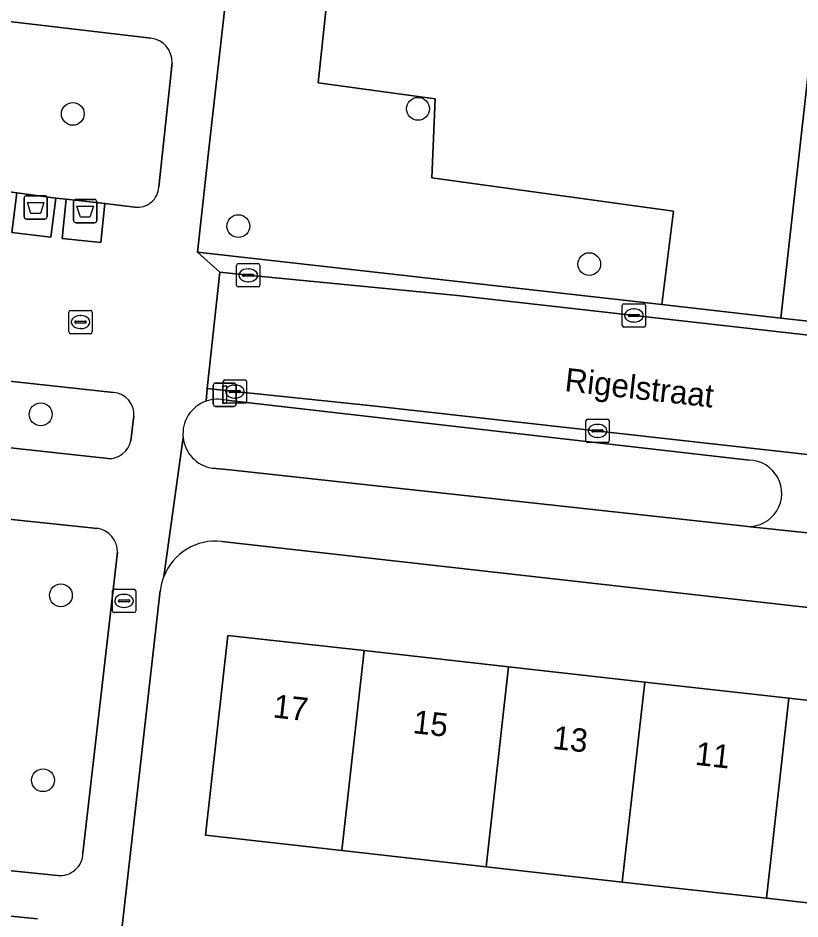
# Model space of a CAD drawing. Extents: x 161928 to 163071, y 386474 to 387428.
# Drawn here: x 162089.79 to 162123.29, y 386856.66 to 386895.27 of the extents above; entities that cross this region are included whole.
import ezdxf

# ---------------------------------------------------------------- set-up
doc = ezdxf.new("R2010")
doc.units = 0
for name, color, linetype in [('IMGEO_Afval_apart_plaats', 7, 'Continuous'), ('IMGEO_Boom', 7, 'Continuous'), ('IMGEO_Brandkraan', 7, 'Continuous'), ('IMGEO_Erf', 7, 'Continuous'), ('IMGEO_Groenvoorziening', 7, 'Continuous'), ('IMGEO_Kolk', 7, 'Continuous'), ('IMGEO_Lichtmast', 7, 'Continuous'), ('IMGEO_Openbare_ruimte_label', 7, 'Continuous'), ('IMGEO_Pand', 7, 'Continuous'), ('IMGEO_Pand_nummerreeks', 7, 'Continuous'), ('IMGEO_Parkeervlak_open', 7, 'Continuous'), ('IMGEO_Rijbaan_lokaal_open', 7, 'Continuous'), ('IMGEO_Voetpad_gesloten', 7, 'Continuous'), ('IMGEO_Voetpad_open', 7, 'Continuous')]:
    doc.layers.add(name, color=color, linetype=linetype)

msp = doc.modelspace()

# ---------------------------------------------------------------- linework, layer by layer
at = {"layer": 'IMGEO_Afval_apart_plaats'}
for p, q in [((162090.152, 386887.655), (162090.942, 386887.655)), ((162090.942, 386887.655), (162090.152, 386887.655)), ((162090.052, 386886.755), (162090.052, 386887.555)), ((162090.052, 386887.555), (162090.052, 386886.755)), ((162091.042, 386887.555), (162091.042, 386886.755)), ((162091.042, 386886.755), (162091.042, 386887.555)), ((162092.177, 386886.595), (162092.177, 386887.395)), ((162092.177, 386887.395), (162092.177, 386886.595)), ((162092.277, 386887.495), (162093.067, 386887.495)), ((162093.067, 386887.495), (162092.277, 386887.495)), ((162093.167, 386887.395), (162093.167, 386886.595)), ((162093.167, 386886.595), (162093.167, 386887.395)), ((162090.942, 386886.655), (162090.152, 386886.655)), ((162090.152, 386886.655), (162090.942, 386886.655)), ((162093.067, 386886.495), (162092.277, 386886.495)), ((162092.277, 386886.495), (162093.067, 386886.495))]:
    msp.add_line(p, q, dxfattribs=at)
for points in [[(162090.195, 386887.369), (162090.899, 386887.369), (162090.75, 386886.899), (162090.344, 386886.899), (162090.195, 386887.369)], [(162092.32, 386887.209), (162093.024, 386887.209), (162092.875, 386886.739), (162092.469, 386886.739), (162092.32, 386887.209)]]:
    msp.add_lwpolyline(points, dxfattribs=at)
for centre, start, end in [((162090.152, 386887.555), 90, 180), ((162090.152, 386887.555), 90, 180), ((162090.942, 386887.555), 0, 90), ((162090.942, 386887.555), 360, 90), ((162092.277, 386887.395), 90, 180), ((162092.277, 386887.395), 90, 180), ((162093.067, 386887.395), 0, 90), ((162093.067, 386887.395), 360, 90), ((162090.152, 386886.755), 180, 270), ((162090.152, 386886.755), 180, 270), ((162090.942, 386886.755), 270, 0), ((162090.942, 386886.755), 270, 0), ((162092.277, 386886.595), 180, 270), ((162092.277, 386886.595), 180, 270), ((162093.067, 386886.595), 270, 0), ((162093.067, 386886.595), 270, 0)]:
    msp.add_arc(centre, 0.1, start, end, dxfattribs=at)
at = {"layer": 'IMGEO_Boom'}
for centre in [(162106.929, 386891.379), (162092.141, 386891.163), (162099.233, 386886.351), (162114.266, 386884.723), (162090.766, 386878.286), (162091.629, 386870.53), (162090.864, 386862.606)]:
    msp.add_circle(centre, 0.489, dxfattribs=at)
at = {"layer": 'IMGEO_Brandkraan'}
for p, q in [((162093.835, 386869.864), (162093.835, 386870.716)), ((162093.91, 386870.79), (162094.762, 386870.79)), ((162094.323, 386870.57), (162094.348, 386870.57)), ((162094.836, 386870.716), (162094.836, 386869.864)), ((162094.094, 386870.284), (162094.094, 386870.296)), ((162094.532, 386870.247), (162094.134, 386870.247)), ((162094.137, 386870.333), (162094.535, 386870.333)), ((162094.578, 386870.296), (162094.578, 386870.284)), ((162094.346, 386870.01), (162094.321, 386870.01)), ((162094.762, 386869.79), (162093.91, 386869.79))]:
    msp.add_line(p, q, dxfattribs=at)
for points in [[(162093.835, 386869.864), (162093.835, 386870.716)], [(162093.91, 386870.79), (162094.762, 386870.79)], [(162094.836, 386870.716), (162094.836, 386869.864)], [(162094.762, 386869.79), (162093.91, 386869.79)]]:
    msp.add_lwpolyline(points, dxfattribs=at)
for centre, radius, start, end in [((162093.912, 386870.714), 0.0765, 91.552, 178.448), ((162093.912, 386870.714), 0.0765, 91.552, 178.448), ((162094.76, 386870.714), 0.0765, 1.552, 88.448), ((162094.76, 386870.714), 0.0765, 1.552, 88.448), ((162094.134, 386870.293), 0.0403, 85.8775, 175.7526), ((162094.131, 386870.283), 0.0366, 178.938, 274.7102), ((162094.535, 386870.29), 0.043, 264.8664, 352.4533), ((162094.539, 386870.295), 0.0386, 1.7309, 96.639), ((162093.912, 386869.866), 0.0765, 181.552, 268.448), ((162093.912, 386869.866), 0.0765, 181.552, 268.448), ((162094.76, 386869.866), 0.0765, 271.552, 358.448), ((162094.76, 386869.866), 0.0765, 271.552, 358.448)]:
    msp.add_arc(centre, radius, start, end, dxfattribs=at)
for centre, major_axis, ratio, start_param, end_param in [((162094.322, 386870.29), (-0.387, 0.002), 0.722429, 4.712389, 7.853982), ((162094.347, 386870.29), (-0.39, 0.002), 0.717154, 1.570796, 4.712389)]:
    msp.add_ellipse(centre, major_axis=major_axis, ratio=ratio, start_param=start_param, end_param=end_param, dxfattribs=at)
at = {"layer": 'IMGEO_Erf'}
for points in [[(162154.85, 386866.488), (162098.526, 386872.838)], [(162095.89, 386870.733), (162093.586, 386850.424), (162103.999, 386849.243), (162104.273, 386851.973), (162109.039, 386851.496), (162114.238, 386850.974), (162113.968, 386848.281), (162115.579, 386848.12), (162115.42, 386846.626), (162113.747, 386846.805), (162113.411, 386843.657), (162108.186, 386844.214), (162103.812, 386844.68), (162104.152, 386847.876), (162101.178, 386848.193), (162100.878, 386845.559), (162096.111, 386846.102), (162095.376, 386838.682), (162101.521, 386837.997), (162107.523, 386837.329), (162113.432, 386836.67), (162119.351, 386836.011), (162125.329, 386835.345)], [(162151.734, 386854.186), (162145.677, 386854.867), (162139.524, 386855.559), (162133.579, 386856.227), (162127.731, 386856.885), (162121.856, 386857.546), (162115.68, 386858.24), (162109.845, 386858.896), (162103.662, 386859.592), (162097.824, 386860.248), (162098.786, 386868.814), (162104.624, 386868.159), (162110.807, 386867.465), (162116.642, 386866.809), (162122.818, 386866.116), (162128.694, 386865.457), (162134.542, 386864.8), (162140.487, 386864.133), (162146.64, 386863.442), (162152.697, 386862.762), (162156.622, 386862.323), (162156.814, 386864.022)]]:
    msp.add_lwpolyline(points, dxfattribs=at)
for centre, radius, start, end in [((162098.259, 386870.469), 2.384, 83.5771, 158.6009), ((162098.249, 386870.471), 2.373, 158.5401, 173.6545)]:
    msp.add_arc(centre, radius, start, end, dxfattribs=at)
at = {"layer": 'IMGEO_Groenvoorziening'}
for points in [[(162124.115, 386897.125), (162124.371, 386899.169), (162124.713, 386901.768), (162124.945, 386903.531), (162126.97, 386903.362), (162127.276, 386905.919), (162127.685, 386909.558), (162125.661, 386909.778), (162104.628, 386912.06), (162106.651, 386930.715), (162107.583, 386930.614), (162108.784, 386940.868), (162103.8, 386941.487), (162099.956, 386907.286), (162104.146, 386906.641), (162102.651, 386892.496), (162107.668, 386891.801), (162107.524, 386888.417), (162117.878, 386886.991), (162117.382, 386882.988), (162122.47, 386882.414)], [(162099.801, 386905.909), (162098.584, 386895.081), (162098.003, 386889.912), (162097.477, 386885.236), (162117.382, 386882.988), (162117.878, 386886.991), (162107.524, 386888.417), (162107.668, 386891.801), (162102.651, 386892.496), (162104.146, 386906.641), (162099.956, 386907.286)], [(162125.347, 386896.927), (162126.226, 386896.855), (162126.494, 386898.944), (162124.371, 386899.169), (162124.115, 386897.125), (162122.47, 386882.414), (162123.771, 386882.267)]]:
    msp.add_lwpolyline(points, close=True, dxfattribs=at)
for points in [[(162088.564, 386895.224), (162087.786, 386888.057), (162089.742, 386887.772), (162091.415, 386887.555), (162091.85, 386887.504), (162093.517, 386887.319), (162094.8, 386887.169)], [(162095.479, 386894.402), (162088.564, 386895.224)], [(162095.826, 386888.035), (162096.393, 386893.355)], [(162086.915, 386879.984), (162086.715, 386878.398), (162086.574, 386877.16), (162093.649, 386876.392)], [(162093.883, 386879.229), (162086.915, 386879.984)], [(162121.116, 386876.319), (162098.714, 386878.889)], [(162094.624, 386877.151), (162094.756, 386878.22)], [(162098.107, 386875.983), (162098.861, 386875.901), (162120.945, 386873.488), (162121.04, 386873.481)], [(162093.197, 386873.401), (162086.247, 386874.125), (162084.603, 386859.23), (162091.479, 386858.53)], [(162092.575, 386859.483), (162094.05, 386872.38)]]:
    msp.add_lwpolyline(points, dxfattribs=at)
for centre, radius, start, end in [((162095.369, 386893.383), 1.025, 358.414, 83.826), ((162094.916, 386888.073), 0.911, 262.6987, 357.6336), ((162093.804, 386878.278), 0.954, 356.5068, 85.2268), ((162098.343, 386877.451), 1.484, 109.351, 186.0645), ((162098.345, 386877.447), 1.488, 75.6517, 109.3908), ((162093.684, 386877.352), 0.961, 267.8829, 347.9158), ((162098.345, 386877.45), 1.486, 186.0234, 260.7881), ((162121.095, 386874.9), 1.42, 267.7809, 89.1512), ((162093.043, 386872.405), 1.008, 358.5718, 81.1828), ((162091.598, 386859.5), 0.977, 263.0077, 359.0079)]:
    msp.add_arc(centre, radius, start, end, dxfattribs=at)
at = {"layer": 'IMGEO_Kolk'}
for p, q in [((162099.158, 386883.818), (162099.158, 386884.67)), ((162099.233, 386884.744), (162100.085, 386884.744)), ((162099.646, 386884.524), (162099.671, 386884.524)), ((162100.159, 386884.67), (162100.159, 386883.818)), ((162099.417, 386884.238), (162099.417, 386884.25)), ((162099.855, 386884.201), (162099.457, 386884.201)), ((162099.46, 386884.287), (162099.858, 386884.287)), ((162099.901, 386884.25), (162099.901, 386884.238)), ((162100.085, 386883.744), (162099.233, 386883.744)), ((162099.669, 386883.964), (162099.644, 386883.964)), ((162115.68, 386882.097), (162115.68, 386882.949)), ((162115.755, 386883.023), (162116.607, 386883.023)), ((162116.681, 386882.949), (162116.681, 386882.097)), ((162091.97, 386881.816), (162091.97, 386882.668)), ((162092.045, 386882.742), (162092.897, 386882.742)), ((162092.971, 386882.668), (162092.971, 386881.816)), ((162115.982, 386882.566), (162116.38, 386882.566)), ((162116.168, 386882.803), (162116.193, 386882.803)), ((162092.229, 386882.236), (162092.229, 386882.248)), ((162092.667, 386882.199), (162092.269, 386882.199)), ((162092.272, 386882.285), (162092.67, 386882.285)), ((162092.458, 386882.522), (162092.483, 386882.522)), ((162092.713, 386882.248), (162092.713, 386882.236)), ((162115.939, 386882.517), (162115.939, 386882.529)), ((162116.377, 386882.48), (162115.979, 386882.48)), ((162116.191, 386882.243), (162116.166, 386882.243)), ((162116.423, 386882.529), (162116.423, 386882.517)), ((162092.481, 386881.962), (162092.456, 386881.962)), ((162116.607, 386882.023), (162115.755, 386882.023)), ((162092.897, 386881.742), (162092.045, 386881.742)), ((162098.583, 386878.835), (162098.583, 386879.687)), ((162098.658, 386879.761), (162099.51, 386879.761)), ((162099.071, 386879.541), (162099.096, 386879.541)), ((162099.584, 386879.687), (162099.584, 386878.835)), ((162098.842, 386879.255), (162098.842, 386879.267)), ((162099.28, 386879.218), (162098.882, 386879.218)), ((162098.885, 386879.304), (162099.283, 386879.304)), ((162099.326, 386879.267), (162099.326, 386879.255)), ((162099.51, 386878.761), (162098.658, 386878.761)), ((162099.094, 386878.981), (162099.069, 386878.981)), ((162114.122, 386877.149), (162114.122, 386878.001)), ((162114.197, 386878.075), (162115.049, 386878.075)), ((162115.123, 386878.001), (162115.123, 386877.149)), ((162114.381, 386877.569), (162114.381, 386877.581)), ((162114.819, 386877.532), (162114.421, 386877.532)), ((162114.424, 386877.618), (162114.822, 386877.618)), ((162114.61, 386877.855), (162114.635, 386877.855)), ((162114.865, 386877.581), (162114.865, 386877.569)), ((162114.633, 386877.295), (162114.608, 386877.295)), ((162115.049, 386877.075), (162114.197, 386877.075))]:
    msp.add_line(p, q, dxfattribs=at)
for points in [[(162099.158, 386883.818), (162099.158, 386884.67)], [(162099.233, 386884.744), (162100.085, 386884.744)], [(162100.159, 386884.67), (162100.159, 386883.818)], [(162100.085, 386883.744), (162099.233, 386883.744)], [(162115.68, 386882.097), (162115.68, 386882.949)], [(162115.755, 386883.023), (162116.607, 386883.023)], [(162116.681, 386882.949), (162116.681, 386882.097)], [(162091.97, 386881.816), (162091.97, 386882.668)], [(162092.045, 386882.742), (162092.897, 386882.742)], [(162092.971, 386882.668), (162092.971, 386881.816)], [(162116.607, 386882.023), (162115.755, 386882.023)], [(162092.897, 386881.742), (162092.045, 386881.742)], [(162098.583, 386878.835), (162098.583, 386879.687)], [(162098.658, 386879.761), (162099.51, 386879.761)], [(162099.584, 386879.687), (162099.584, 386878.835)], [(162099.51, 386878.761), (162098.658, 386878.761)], [(162114.122, 386877.149), (162114.122, 386878.001)], [(162114.197, 386878.075), (162115.049, 386878.075)], [(162115.123, 386878.001), (162115.123, 386877.149)], [(162115.049, 386877.075), (162114.197, 386877.075)]]:
    msp.add_lwpolyline(points, dxfattribs=at)
for centre, radius, start, end in [((162099.235, 386884.668), 0.0765, 91.552, 178.448), ((162099.235, 386884.668), 0.0765, 91.552, 178.448), ((162100.083, 386884.668), 0.0765, 1.552, 88.448), ((162100.083, 386884.668), 0.0765, 1.552, 88.448), ((162099.457, 386884.247), 0.0403, 85.8775, 175.7526), ((162099.454, 386884.237), 0.0366, 178.938, 274.7102), ((162099.858, 386884.244), 0.043, 264.8664, 352.4533), ((162099.862, 386884.249), 0.0386, 1.7309, 96.639), ((162099.235, 386883.82), 0.0765, 181.552, 268.448), ((162099.235, 386883.82), 0.0765, 181.552, 268.448), ((162100.083, 386883.82), 0.0765, 271.552, 358.448), ((162100.083, 386883.82), 0.0765, 271.552, 358.448), ((162115.757, 386882.947), 0.0765, 91.552, 178.448), ((162115.757, 386882.947), 0.0765, 91.552, 178.448), ((162116.605, 386882.947), 0.0765, 1.552, 88.448), ((162116.605, 386882.947), 0.0765, 1.552, 88.448), ((162092.047, 386882.666), 0.0765, 91.552, 178.448), ((162092.047, 386882.666), 0.0765, 91.552, 178.448), ((162092.895, 386882.666), 0.0765, 1.552, 88.448), ((162092.895, 386882.666), 0.0765, 1.552, 88.448), ((162115.979, 386882.526), 0.0403, 85.8775, 175.7526), ((162116.384, 386882.528), 0.0386, 1.7309, 96.639), ((162092.269, 386882.245), 0.0403, 85.8775, 175.7526), ((162092.266, 386882.235), 0.0366, 178.938, 274.7102), ((162092.67, 386882.242), 0.043, 264.8664, 352.4533), ((162092.674, 386882.247), 0.0386, 1.7309, 96.639), ((162115.976, 386882.516), 0.0366, 178.938, 274.7102), ((162116.38, 386882.523), 0.043, 264.8664, 352.4533), ((162092.047, 386881.818), 0.0765, 181.552, 268.448), ((162092.047, 386881.818), 0.0765, 181.552, 268.448), ((162092.895, 386881.818), 0.0765, 271.552, 358.448), ((162092.895, 386881.818), 0.0765, 271.552, 358.448), ((162115.757, 386882.099), 0.0765, 181.552, 268.448), ((162115.757, 386882.099), 0.0765, 181.552, 268.448), ((162116.605, 386882.099), 0.0765, 271.552, 358.448), ((162116.605, 386882.099), 0.0765, 271.552, 358.448), ((162098.66, 386879.685), 0.0765, 91.552, 178.448), ((162098.66, 386879.685), 0.0765, 91.552, 178.448), ((162099.508, 386879.685), 0.0765, 1.552, 88.448), ((162099.508, 386879.685), 0.0765, 1.552, 88.448), ((162098.882, 386879.264), 0.0403, 85.8775, 175.7526), ((162098.879, 386879.254), 0.0366, 178.938, 274.7102), ((162099.283, 386879.261), 0.043, 264.8664, 352.4533), ((162099.287, 386879.266), 0.0386, 1.7309, 96.639), ((162098.66, 386878.837), 0.0765, 181.552, 268.448), ((162098.66, 386878.837), 0.0765, 181.552, 268.448), ((162099.508, 386878.837), 0.0765, 271.552, 358.448), ((162099.508, 386878.837), 0.0765, 271.552, 358.448), ((162114.199, 386877.999), 0.0765, 91.552, 178.448), ((162114.199, 386877.999), 0.0765, 91.552, 178.448), ((162115.047, 386877.999), 0.0765, 1.552, 88.448), ((162115.047, 386877.999), 0.0765, 1.552, 88.448), ((162114.421, 386877.578), 0.0403, 85.8775, 175.7526), ((162114.418, 386877.568), 0.0366, 178.938, 274.7102), ((162114.822, 386877.575), 0.043, 264.8664, 352.4533), ((162114.826, 386877.58), 0.0386, 1.7309, 96.639), ((162114.199, 386877.151), 0.0765, 181.552, 268.448), ((162114.199, 386877.151), 0.0765, 181.552, 268.448), ((162115.047, 386877.151), 0.0765, 271.552, 358.448), ((162115.047, 386877.151), 0.0765, 271.552, 358.448)]:
    msp.add_arc(centre, radius, start, end, dxfattribs=at)
for centre, major_axis, ratio, start_param, end_param in [((162099.645, 386884.244), (-0.387, 0.002), 0.722429, 4.712389, 7.853982), ((162099.67, 386884.244), (-0.39, 0.002), 0.717154, 1.570796, 4.712389), ((162116.167, 386882.523), (-0.387, 0.002), 0.722429, 4.712389, 7.853982), ((162116.192, 386882.523), (-0.39, 0.002), 0.717154, 1.570796, 4.712389), ((162092.457, 386882.242), (-0.387, 0.002), 0.722429, 4.712389, 7.853982), ((162092.482, 386882.242), (-0.39, 0.002), 0.717154, 1.570796, 4.712389), ((162099.07, 386879.261), (-0.387, 0.002), 0.722429, 4.712389, 7.853982), ((162099.095, 386879.261), (-0.39, 0.002), 0.717154, 1.570796, 4.712389), ((162114.609, 386877.575), (-0.387, 0.002), 0.722429, 4.712389, 7.853982), ((162114.634, 386877.575), (-0.39, 0.002), 0.717154, 1.570796, 4.712389)]:
    msp.add_ellipse(centre, major_axis=major_axis, ratio=ratio, start_param=start_param, end_param=end_param, dxfattribs=at)
at = {"layer": 'IMGEO_Lichtmast'}
for p, q in [((162098.154, 386878.726), (162098.154, 386879.526)), ((162098.154, 386879.526), (162098.154, 386878.726)), ((162098.254, 386879.626), (162099.044, 386879.626)), ((162099.044, 386879.626), (162098.254, 386879.626)), ((162099.144, 386879.526), (162099.144, 386878.726)), ((162099.144, 386878.726), (162099.144, 386879.526)), ((162099.044, 386878.626), (162098.254, 386878.626)), ((162098.254, 386878.626), (162099.044, 386878.626))]:
    msp.add_line(p, q, dxfattribs=at)
msp.add_lwpolyline([(162098.574, 386879.501), (162098.724, 386879.501), (162098.724, 386878.751), (162098.574, 386878.751), (162098.574, 386879.501)], dxfattribs=at)
for centre, start, end in [((162098.254, 386879.526), 90, 180), ((162098.254, 386879.526), 90, 180), ((162099.044, 386879.526), 0, 90), ((162099.044, 386879.526), 360, 90), ((162098.254, 386878.726), 180, 270), ((162098.254, 386878.726), 180, 270), ((162099.044, 386878.726), 270, 0), ((162099.044, 386878.726), 270, 0)]:
    msp.add_arc(centre, 0.1, start, end, dxfattribs=at)
at = {"layer": 'IMGEO_Pand'}
for points in [[(162104.624, 386868.159), (162098.786, 386868.814), (162097.824, 386860.248), (162103.662, 386859.592)], [(162110.807, 386867.465), (162104.624, 386868.159), (162103.662, 386859.592), (162109.845, 386858.896)], [(162109.845, 386858.896), (162115.68, 386858.24), (162116.642, 386866.809), (162110.807, 386867.465)], [(162122.818, 386866.116), (162116.642, 386866.809), (162115.68, 386858.24), (162121.856, 386857.546)], [(162128.694, 386865.457), (162122.818, 386866.116), (162121.856, 386857.546), (162127.731, 386856.885)]]:
    msp.add_lwpolyline(points, close=True, dxfattribs=at)
at = {"layer": 'IMGEO_Parkeervlak_open'}
msp.add_lwpolyline([(162090.621, 386856.66), (162085.772, 386857.147)], dxfattribs=at)
at = {"layer": 'IMGEO_Rijbaan_lokaal_open'}
for points in [[(162108.615, 386883.376), (162099.659, 386884.244), (162098.436, 386884.38), (162097.894, 386879.394), (162099.084, 386879.261), (162104.979, 386878.654), (162145.577, 386874.11)], [(162159.519, 386870.956), (162159.784, 386873.278), (162160.048, 386875.599), (162160.06, 386875.774), (162160.056, 386875.949), (162160.037, 386876.123), (162160.002, 386876.295), (162159.952, 386876.462), (162159.887, 386876.625), (162159.808, 386876.781), (162159.716, 386876.93), (162159.61, 386877.07), (162159.492, 386877.199), (162159.363, 386877.318), (162159.225, 386877.425), (162159.077, 386877.519), (162158.921, 386877.599), (162158.759, 386877.665), (162158.591, 386877.716), (162158.42, 386877.752), (162158.322, 386877.766), (162108.615, 386883.376)]]:
    msp.add_lwpolyline(points, dxfattribs=at)
at = {"layer": 'IMGEO_Voetpad_gesloten'}
for points in [[(162091.415, 386887.555), (162089.742, 386887.772), (162089.531, 386886.083), (162091.205, 386885.885)], [(162093.517, 386887.319), (162091.85, 386887.504), (162091.68, 386885.824), (162093.34, 386885.656)]]:
    msp.add_lwpolyline(points, close=True, dxfattribs=at)
at = {"layer": 'IMGEO_Voetpad_open'}
for points in [[(162097.851, 386878.851), (162097.894, 386879.394), (162098.436, 386884.38), (162097.477, 386885.236), (162098.003, 386889.912), (162098.584, 386895.081), (162099.801, 386905.909), (162099.956, 386907.286), (162103.8, 386941.487), (162104.108, 386944.29)], [(162088.711, 386896.367), (162088.706, 386896.314), (162088.564, 386895.224), (162095.479, 386894.402)], [(162096.393, 386893.355), (162095.826, 386888.035)], [(162094.8, 386887.169), (162093.517, 386887.319), (162093.34, 386885.656), (162091.68, 386885.824), (162091.85, 386887.504), (162091.415, 386887.555), (162091.205, 386885.885), (162089.531, 386886.083), (162089.742, 386887.772), (162087.786, 386888.057), (162087.574, 386886.163), (162086.926, 386880.164), (162086.915, 386879.984), (162093.883, 386879.229)], [(162123.771, 386882.267), (162122.47, 386882.414), (162117.382, 386882.988), (162097.477, 386885.236), (162098.436, 386884.38), (162099.659, 386884.244), (162108.615, 386883.376), (162158.322, 386877.766)], [(162145.577, 386874.11), (162104.979, 386878.654), (162099.084, 386879.261), (162097.894, 386879.394), (162097.851, 386878.851)], [(162098.714, 386878.889), (162121.116, 386876.319)], [(162094.756, 386878.22), (162094.624, 386877.151)], [(162093.649, 386876.392), (162086.574, 386877.16), (162086.247, 386874.125), (162093.197, 386873.401)], [(162096.867, 386877.294), (162096.04, 386871.339)], [(162096.04, 386871.339), (162096.867, 386877.294)], [(162125.636, 386872.996), (162121.04, 386873.481), (162120.945, 386873.488), (162098.861, 386875.901), (162098.107, 386875.983)], [(162121.04, 386873.481), (162125.636, 386872.996)], [(162098.526, 386872.838), (162154.85, 386866.488)], [(162094.05, 386872.38), (162092.575, 386859.483)], [(162083.355, 386759.809), (162084.229, 386767.795), (162084.377, 386769.109), (162089.833, 386817.598), (162090.441, 386822.62), (162090.455, 386822.824), (162092.006, 386836.491), (162093.369, 386848.507), (162093.586, 386850.424), (162095.89, 386870.733)], [(162091.479, 386858.53), (162084.603, 386859.23), (162084.512, 386858.277)], [(162085.386, 386857.195), (162085.772, 386857.147), (162090.621, 386856.66)]]:
    msp.add_lwpolyline(points, dxfattribs=at)
for centre, radius, start, end in [((162095.369, 386893.383), 1.025, 358.414, 83.826), ((162094.916, 386888.073), 0.911, 262.6987, 357.6336), ((162093.804, 386878.278), 0.954, 356.5068, 85.2268), ((162098.343, 386877.451), 1.484, 109.351, 186.0645), ((162098.345, 386877.447), 1.488, 75.6517, 109.3908), ((162093.684, 386877.352), 0.961, 267.8829, 347.9158), ((162098.345, 386877.45), 1.486, 186.0234, 260.7881), ((162121.095, 386874.9), 1.42, 267.7809, 89.1512), ((162093.043, 386872.405), 1.008, 358.5718, 81.1828), ((162098.259, 386870.469), 2.384, 83.5771, 158.6009), ((162098.249, 386870.471), 2.373, 158.5401, 173.6545), ((162091.598, 386859.5), 0.977, 263.0077, 359.0079)]:
    msp.add_arc(centre, radius, start, end, dxfattribs=at)

# ---------------------------------------------------------------- texts
at = {"layer": 'IMGEO_Openbare_ruimte_label'}
msp.add_text('Rigelstraat', height=1, rotation=353.6282, dxfattribs=at).set_placement((162113.184, 386879.286))
at = {"layer": 'IMGEO_Pand_nummerreeks'}
for s, p in [('17', (162100.685, 386865.301)), ('15', (162106.675, 386864.628)), ('13', (162112.665, 386863.956)), ('11', (162118.768, 386863.271))]:
    msp.add_text(s, height=1, rotation=353.5948, dxfattribs=at).set_placement(p)

doc.saveas('drawing.dxf')
